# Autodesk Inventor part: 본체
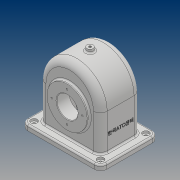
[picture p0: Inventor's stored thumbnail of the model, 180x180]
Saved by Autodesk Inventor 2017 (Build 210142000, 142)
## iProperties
Part Number: 본체
Material: 일반
Document SubType Name: Modeling
Designer: 20
Density: 1 g/cm^3
Appearance: 기본값
Mass: 404.475 g
Surface Area: 1182.21 cm^2
Volume: 404.475 cm^3
Author: 20
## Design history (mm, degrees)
sketch "스케치1"
  geometry: L1 (58, 0)-(58, -78); L2 (58, -78)-(-58, -78); L3 (-58, -78)-(-58, 0); A1 r 58 centre (0, 0) between (58, 0) and (-58, 0); 1 further point
  constraints: 6 end point, 2 point on circle, 2 tangent, 2 vertical, 1 centre point, 1 coincident, 1 horizontal
  dimensions: "d0" = 116 diameter of A1; "d1" = 78 distance from line of L2 point (0, 0)
extrude "돌출1" new body sketch "스케치1" stored distance "d2" = 77; taper "d3" = 0 deg
sketch "스케치2"
  geometry: L1 (52, 0)-(52, -78); L2 (52, -78)-(-52, -78); L3 (-52, -78)-(-52, 0); L4 (-58, -78)-(58, -78) reference; A1 r 52 centre (0, 0) between (52, 0) and (-52, 0); 1 further point
  constraints: 6 end point, 2 point on circle, 2 tangent, 2 vertical, 1 centre point, 1 coincident, 1 collinear, 1 horizontal
  dimensions: "d4" = 104 diameter of A1
extrude "돌출2" cut sketch "스케치2" stored distance "d5" = 67; taper "d6" = 0 deg
sketch "스케치3"
  geometry: L1 (-58, -78)-(58, -78) reference; C1 r 38 at (0, -13); 1 further point
  constraints: 1 centre point, 1 vertical alignment
  dimensions: "d7" = 76 diameter of C1; "d8" = 65 distance from line of L1 C1.centre
extrude "돌출3" join sketch "스케치3" distance "d9" = 5; taper "d10" = 0 deg
sketch "스케치4"
  geometry: L1 (58, 78)-(-58, 78) reference; C1 r 38 at (0, 13); 1 further point
  constraints: 1 centre point, 1 vertical alignment
  dimensions: "d11" = 76 diameter of C1; "d12" = 65 distance from line of L1 C1.centre
extrude "돌출4" join sketch "스케치4" distance "d13" = 10; taper "d14" = 0 deg
sketch "스케치5"
  geometry: L1 (-58, 78)-(58, 78) reference; C1 r 28 at (0, 13); 1 further point
  constraints: 1 centre point, 1 vertical alignment
  dimensions: "d15" = 56 diameter of C1; "d16" = 65 distance from line of L1 C1.centre
extrude "돌출5" join sketch "스케치5" distance "d17" = 14; taper "d18" = 0 deg
sketch "스케치6"
  geometry: C1 r 38 at (0, 0) reference; C2 r 20 at (0, 0); 1 further point
  constraints: 1 centre point, 1 coincident
  dimensions: "d19" = 40 diameter of C2
extrude "돌출6" cut sketch "스케치6" stored distance "d20" = 14; taper "d21" = 0 deg
sketch "스케치7"
  geometry: L1 (133, -93.5)-(-17, -93.5); L2 (-17, -93.5)-(-17, 16.5); L3 (-17, 16.5)-(133, 16.5); L4 (133, 16.5)-(133, -93.5); L5 (133, -93.5)-(-17, 16.5); L6 (-17, -93.5)-(133, 16.5); L7 (110, -72)-(6, -72) reference; L8 (110, -5)-(110, -72) reference; L9 (6, -5)-(110, -5) reference; L10 (6, -72)-(6, -5) reference; 1 further point
  constraints: 12 end point, 2 midpoint, 2 parallel, 1 horizontal, 1 perpendicular
  dimensions: "d22" = 150 distance of L2.end L3.end; "d23" = 110 distance of L1.end L2.end
extrude "돌출7" join sketch "스케치7" distance "d24" = 10; taper "d25" = 0 deg
node "작업 평면1"
sketch "스케치8"
  geometry: C1 r 6 at (75, 55); 1 further point
  constraints: 1 centre point, 1 coincident
  dimensions: "d27" = 12 diameter of C1
extrude "돌출8" join sketch "스케치8" stored distance "d28" = 10; taper "d29" = 0 deg
hole "구멍1" diameter "d32" = 4.459; stored, may be unused: countersink angle "d36" = 90 deg, drill point angle "d38" = 0 deg; dims "d30" = 10, "d31" = 10, "d33" = 10, "d34" = 4, "d35" = 2, "d37" = 50
fillet "모깎기1" dims "d39" = 12
sketch "스케치9"
  geometry: A1 r 12 centre (-121, -81.5) between (-133, -81.5) and (-121, -93.5) reference; 2 further points
  constraints: 1 coincident
hole "구멍2" sketch "스케치9" at (-121, -81.5) diameter "d40" = 5; stored, may be unused: countersink angle "d44" = 90 deg, drill point angle "d46" = 0 deg; dims "d41" = 10, "d42" = 12, "d43" = 4, "d45" = 50
sketch "스케치10"
  geometry: L1 (68, 0)-(0, 0) reference; L2 (78, -4.5)-(78, 81.5) reference; 2 further points
  constraints: 1 other
  dimensions: "d47" = 38.5 distance from line of L1 point (38, 38.5); "d48" = 40 distance from line of L2 point (38, 38.5)
feature "엠보싱1" sketch "스케치10" dims "d49" = 0.5, "d50" = 0
feature "면 기울기1" dims angle "d51" = 40 deg
feature "면 기울기2" dims angle "d52" = 5 deg
sketch "스케치11" dims "d53" = 58
  geometry: C1 r 39.747 at (0, 0) reference; 3 further points
  constraints: 2 vertical alignment, 1 coincident, 2 other
hole "구멍3" sketch "스케치11" at (0, 29) diameter "d54" = 3.242; stored, may be unused: countersink angle "d58" = 90 deg, drill point angle "d60" = 118 deg; dims "d55" = 8, "d56" = 12, "d57" = 4, "d59" = 10
sketch "스케치12" dims "d64" = 58
  geometry: C1 r 20 at (0, 0) reference; 3 further points
  constraints: 2 vertical alignment, 1 coincident, 2 other
hole "구멍4" sketch "스케치12" at (0, -29) diameter "d65" = 3.242; stored, may be unused: countersink angle "d69" = 90 deg, drill point angle "d71" = 118 deg; dims "d66" = 8, "d67" = 12, "d68" = 4, "d70" = 10
fillet "모깎기2" dims "d75" = 13
fillet "모깎기3" dims "d76" = 8
fillet "모깎기4" dims "d77" = 3
fillet "모깎기5" dims "d78" = 3
fillet "모깎기6" dims "d79" = 3
fillet "모깎기7" dims "d80" = 3
chamfer "모따기1" distance "d81" = 1; stored, may be unused: second distance "d82" = 2, angle "d83" = 45 deg
fillet "모깎기8" dims "d84" = 3
node "솔리드1"
mirror "미러1"
mirror "미러2"
pattern_circular "원형 패턴1" dims angle "d62" = 360 deg
pattern_circular "원형 패턴2" dims angle "d73" = 360 deg
other parameters: "d26" = -142
